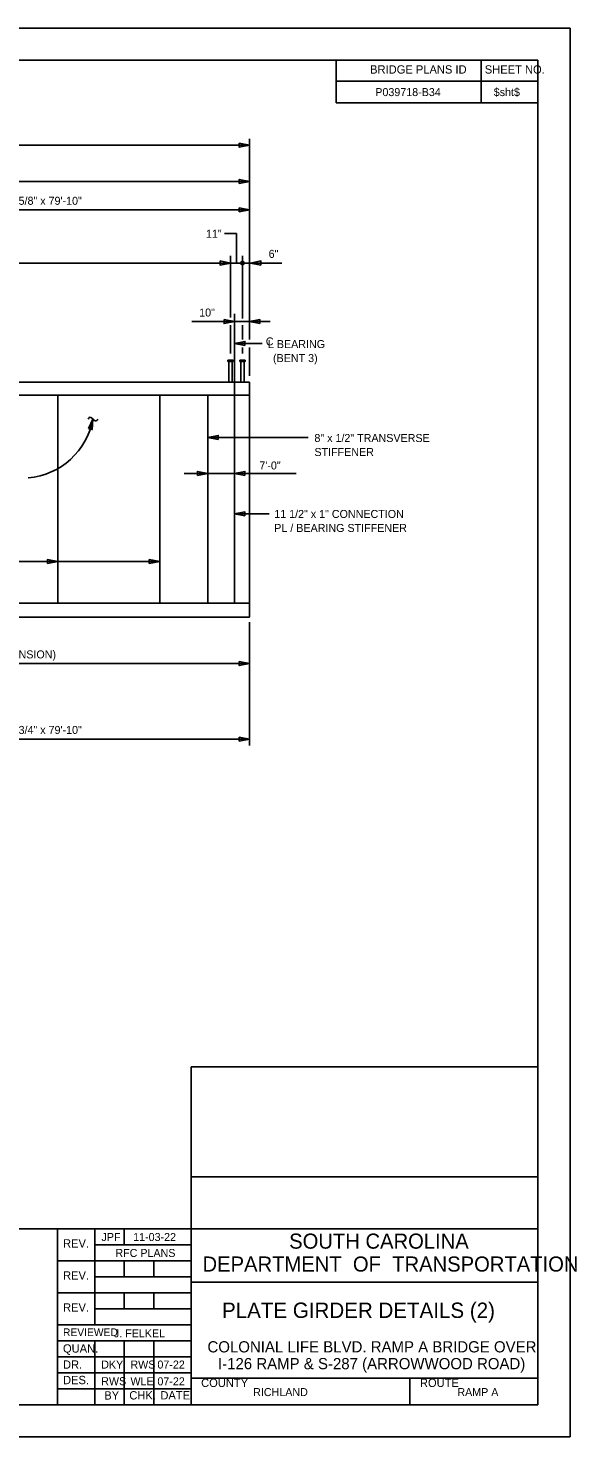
# Model space of a CAD drawing. Extents: x -383 to 3, y -322 to -94.
# Drawn here: x -195 to -160.8, y -187.5 to -99.5 of the extents above; entities that cross this region are included whole.
import ezdxf

# ---------------------------------------------------------------- set-up
doc = ezdxf.new("R2010")
doc.units = 0
for name, color, linetype in [('BR_AUTO DIMENSION', 7, 'Continuous'), ('BR_BORDER LINES', 7, 'Continuous'), ('BR_CENTER LINES', 7, 'Continuous'), ('BR_STRUCTURAL STEEL', 7, 'Continuous'), ('BR_TEXT', 7, 'Continuous'), ('Default', 7, 'Continuous'), ('Level 31', 7, 'Continuous')]:
    doc.layers.add(name, color=color, linetype=linetype)

msp = doc.modelspace()

# ---------------------------------------------------------------- linework, layer by layer
at = {"layer": 'BR_AUTO DIMENSION'}
for p, q in [((-181.19, -118.929), (-181.19, -106.393)), ((-278.395, -106.806), (-181.19, -106.806)), ((-221.135, -109.064), (-181.19, -109.064)), ((-207.802, -110.841), (-181.19, -110.841)), ((-217.663, -114.159), (-182.385, -114.159)), ((-182.385, -117.562), (-182.385, -113.71)), ((-179.182, -114.159), (-182.385, -114.159)), ((-181.635, -117.621), (-181.635, -113.71)), ((-184.789, -117.821), (-179.912, -117.821)), ((-182.385, -119.81), (-182.385, -118.048)), ((-181.635, -118.929), (-181.635, -118.048)), ((-182.135, -119.183), (-180.412, -119.183)), ((-181.635, -119.81), (-181.635, -119.447)), ((-181.19, -121.218), (-181.19, -119.447)), ((-183.802, -125.056), (-177.538, -125.056)), ((-178.277, -127.307), (-185.28, -127.307)), ((-182.135, -129.829), (-179.961, -129.829)), ((-186.804, -132.816), (-283.86, -132.816)), ((-181.19, -136.592), (-181.19, -144.298)), ((-181.19, -139.18), (-210.469, -139.18)), ((-207.802, -143.898), (-181.19, -143.898))]:
    msp.add_line(p, q, dxfattribs=at)
for points in [[(-181.84, -106.681), (-181.19, -106.806), (-181.84, -106.931)], [(-181.84, -109.189), (-181.19, -109.064), (-181.84, -108.939)], [(-181.84, -110.966), (-181.19, -110.841), (-181.84, -110.716)], [(-183.035, -114.034), (-182.385, -114.159), (-183.035, -114.284)], [(-180.485, -114.284), (-181.135, -114.159), (-180.485, -114.034)], [(-182.785, -117.696), (-182.135, -117.821), (-182.785, -117.946)], [(-180.54, -117.946), (-181.19, -117.821), (-180.54, -117.696)], [(-181.485, -119.308), (-182.135, -119.183), (-181.485, -119.058)], [(-191.261, -124.504), (-190.978, -123.906), (-191.019, -124.566)], [(-183.152, -125.181), (-183.802, -125.056), (-183.152, -124.931)], [(-184.452, -127.432), (-183.802, -127.307), (-184.452, -127.182)], [(-181.485, -127.432), (-182.135, -127.307), (-181.485, -127.182)], [(-181.485, -129.954), (-182.135, -129.829), (-181.485, -129.704)], [(-193.816, -132.941), (-193.166, -132.816), (-193.816, -132.691)], [(-187.454, -132.941), (-186.804, -132.816), (-187.454, -132.691)], [(-181.84, -139.055), (-181.19, -139.18), (-181.84, -139.305)], [(-181.84, -143.773), (-181.19, -143.898), (-181.84, -144.023)]]:
    msp.add_lwpolyline(points, close=True, dxfattribs=at)
msp.add_lwpolyline([(-182.01, -114.159), (-182.01, -112.317), (-182.75, -112.317)], dxfattribs=at)
msp.add_lwpolyline([(-182.01, -114.159), (-182.01, -112.317), (-182.75, -112.317)], dxfattribs=at)
msp.add_circle((-181.635, -114.159), 0.111, dxfattribs=at)
msp.add_arc((-195.403, -123.102), 4.497, 274.96239, 349.7037, dxfattribs=at)
at = {"layer": 'BR_BORDER LINES'}
for p, q in [((-163.178, -101.489), (-297.843, -101.489)), ((-175.788, -104.156), (-175.788, -101.489)), ((-166.722, -104.156), (-166.722, -101.489)), ((-163.178, -185.489), (-163.178, -101.489)), ((-175.788, -102.808), (-163.178, -102.808)), ((-166.722, -102.808), (-163.178, -102.808)), ((-163.178, -104.156), (-175.788, -104.156)), ((-184.846, -185.489), (-184.846, -164.383)), ((-184.846, -164.383), (-163.178, -164.383)), ((-184.845, -171.242), (-163.178, -171.242)), ((-214.64, -174.489), (-193.18, -174.489)), ((-193.18, -185.489), (-193.18, -174.489)), ((-193.18, -174.489), (-163.178, -174.489)), ((-190.846, -174.489), (-190.846, -180.489)), ((-189.013, -175.489), (-189.013, -174.489)), ((-190.846, -175.489), (-184.846, -175.489)), ((-193.18, -176.489), (-184.846, -176.489)), ((-189.013, -177.489), (-189.013, -176.489)), ((-187.179, -177.489), (-187.179, -176.489)), ((-190.846, -177.489), (-184.846, -177.489)), ((-193.18, -178.489), (-184.846, -178.489)), ((-189.013, -179.489), (-189.013, -178.489)), ((-187.179, -179.489), (-187.179, -178.489)), ((-184.846, -177.822), (-184.846, -177.822)), ((-184.846, -177.823), (-163.178, -177.823)), ((-190.846, -179.489), (-184.846, -179.489)), ((-193.18, -180.489), (-184.846, -180.489)), ((-193.18, -181.489), (-184.846, -181.489)), ((-190.846, -181.489), (-190.846, -185.489)), ((-189.013, -181.489), (-189.013, -185.489)), ((-187.179, -181.489), (-187.179, -185.489)), ((-193.18, -182.489), (-184.846, -182.489)), ((-193.18, -183.489), (-184.846, -183.489)), ((-184.846, -183.823), (-163.178, -183.823)), ((-184.456, -183.823), (-163.178, -183.823)), ((-171.179, -185.489), (-171.179, -183.823)), ((-193.18, -184.489), (-184.846, -184.489)), ((-297.843, -185.489), (-163.178, -185.489))]:
    msp.add_line(p, q, dxfattribs=at)
at = {"layer": 'BR_CENTER LINES'}
msp.add_line((-182.135, -117.333), (-182.135, -122.412), dxfattribs=at)
at = {"layer": 'BR_STRUCTURAL STEEL'}
for p, q in [((-207.802, -121.6), (-181.19, -121.6)), ((-181.19, -122.412), (-181.19, -121.6)), ((-278.395, -122.412), (-181.19, -122.412)), ((-193.166, -122.412), (-193.166, -135.412)), ((-186.804, -122.412), (-186.804, -135.412)), ((-183.802, -122.412), (-183.802, -135.412)), ((-182.135, -122.412), (-182.135, -135.412)), ((-181.19, -122.412), (-181.19, -135.412)), ((-278.395, -135.412), (-181.19, -135.412)), ((-181.19, -135.412), (-181.19, -136.287)), ((-207.802, -136.287), (-181.19, -136.287))]:
    msp.add_line(p, q, dxfattribs=at)
at = {"layer": 'BR_TEXT'}
for p, q in [((-191.238, -123.853), (-191.281, -123.914)), ((-190.897, -123.98), (-191.06, -123.831)), ((-190.664, -123.914), (-190.693, -123.96))]:
    msp.add_line(p, q, dxfattribs=at)
for centre, radius, start, end in [((-191.141, -123.906), 0.111, 43.45189, 151.73747), ((-190.803, -123.899), 0.125, 221.00704, 330.80591)]:
    msp.add_arc(centre, radius, start, end, dxfattribs=at)
at = {"layer": 'Default'}
for p, q in [((-182.557, -120.225), (-182.557, -120.319)), ((-182.557, -120.225), (-182.213, -120.225)), ((-182.557, -120.319), (-182.213, -120.319)), ((-182.494, -120.319), (-182.494, -121.6)), ((-182.276, -120.319), (-182.276, -121.6)), ((-182.213, -120.225), (-182.213, -120.319)), ((-181.807, -120.225), (-181.807, -120.319)), ((-181.807, -120.225), (-181.463, -120.225)), ((-181.807, -120.319), (-181.463, -120.319)), ((-181.744, -120.319), (-181.744, -121.6)), ((-181.526, -120.319), (-181.526, -121.6)), ((-181.463, -120.225), (-181.463, -120.319))]:
    msp.add_line(p, q, dxfattribs=at)
at = {"layer": 'Level 31'}
msp.add_line((-174.011, -179.583), (-174.011, -179.583), dxfattribs=at)
msp.add_lwpolyline([(-305.176, -187.489), (-161.176, -187.489), (-161.176, -99.489), (-305.176, -99.489)], close=True, dxfattribs=at)

# ---------------------------------------------------------------- texts
at = {"layer": 'BR_AUTO DIMENSION'}
for s, p in [('PL 22" x 1 5/8" x 79\'-10"', (-198.865, -110.522)), ('11"', (-183.917, -112.585)), ('6"', (-180, -113.839)), ('10"', (-184.338, -117.502)), ('(TENSION)', (-196.697, -138.86)), ('PL 22" x 1 3/4" x 79\'-10"', (-198.865, -143.579))]:
    msp.add_text(s, height=0.5, rotation=360, dxfattribs=at).set_placement(p)
msp.add_text('7\'-0"', height=0.5, dxfattribs=at).set_placement((-180.579, -127.057))
at = {"layer": 'BR_TEXT'}
for s, height, p in [('BRIDGE PLANS ID', 0.52, (-173.663, -102.327)), ('SHEET NO.', 0.52, (-166.499, -102.327)), ('P039718-B34', 0.5, (-173.338, -103.732)), ('$sht$', 0.5, (-165.939, -103.732)), ('C', 0.5, (-180.176, -119.306)), ('L BEARING', 0.5, (-180.044, -119.473)), ('(BENT 3)', 0.5, (-179.726, -120.348)), ('11 1/2" x 1" CONNECTION ', 0.5, (-179.648, -130.086)), ('PL / BEARING STIFFENER', 0.5, (-179.648, -130.961)), ('JPF', 0.5, (-190.438, -175.257)), ('11-03-22', 0.5, (-188.461, -175.257)), ('SOUTH CAROLINA', 0.94348, (-178.718, -175.735)), ('REV.', 0.52, (-192.841, -175.667)), ('RFC PLANS', 0.5, (-189.572, -176.253)), ('DEPARTMENT  OF  TRANSPORTATION', 0.94348, (-184.129, -177.166)), ('REV.', 0.52, (-192.841, -177.667)), ('REV.', 0.52, (-192.841, -179.667)), ('PLATE GIRDER DETAILS (2)', 0.96, (-182.913, -180.063)), ('REVIEWED', 0.48, (-192.843, -181.195)), ('J. FELKEL', 0.5, (-189.664, -181.272)), ('QUAN.', 0.52, (-192.846, -182.229)), ('COLONIAL LIFE BLVD. RAMP A BRIDGE OVER', 0.7, (-183.82, -182.216)), ('DR.', 0.52, (-192.845, -183.235)), ('DKY', 0.5, (-190.457, -183.224)), ('RWS', 0.5, (-188.632, -183.224)), ('07-22', 0.5, (-186.946, -183.224)), ('I-126 RAMP & S-287 (ARROWWOOD ROAD)', 0.7, (-183.162, -183.266)), ('DES.', 0.52, (-192.841, -184.2)), ('RWS', 0.5, (-190.457, -184.263)), ('WLE', 0.5, (-188.63, -184.263)), ('07-22', 0.5, (-186.946, -184.272)), ('COUNTY', 0.52, (-184.217, -184.376)), ('ROUTE', 0.52, (-170.55, -184.376)), ('BY', 0.52, (-190.265, -185.161)), ('CHK.', 0.52, (-188.701, -185.156)), ('DATE', 0.52, (-186.761, -185.156)), ('RICHLAND', 0.5, (-180.968, -184.944)), ('RAMP A', 0.5, (-168.212, -184.944))]:
    msp.add_text(s, height=height, dxfattribs=at).set_placement(p)
for s, p in [('8" x 1/2" TRANSVERSE', (-177.14, -125.341)), ('STIFFENER', (-177.14, -126.216))]:
    msp.add_text(s, height=0.5, rotation=360, dxfattribs=at).set_placement(p)

doc.saveas('drawing.dxf')
